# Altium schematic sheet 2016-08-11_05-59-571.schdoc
size 422 x 220 mm; SheetNumber: 1; SheetTotal: 1
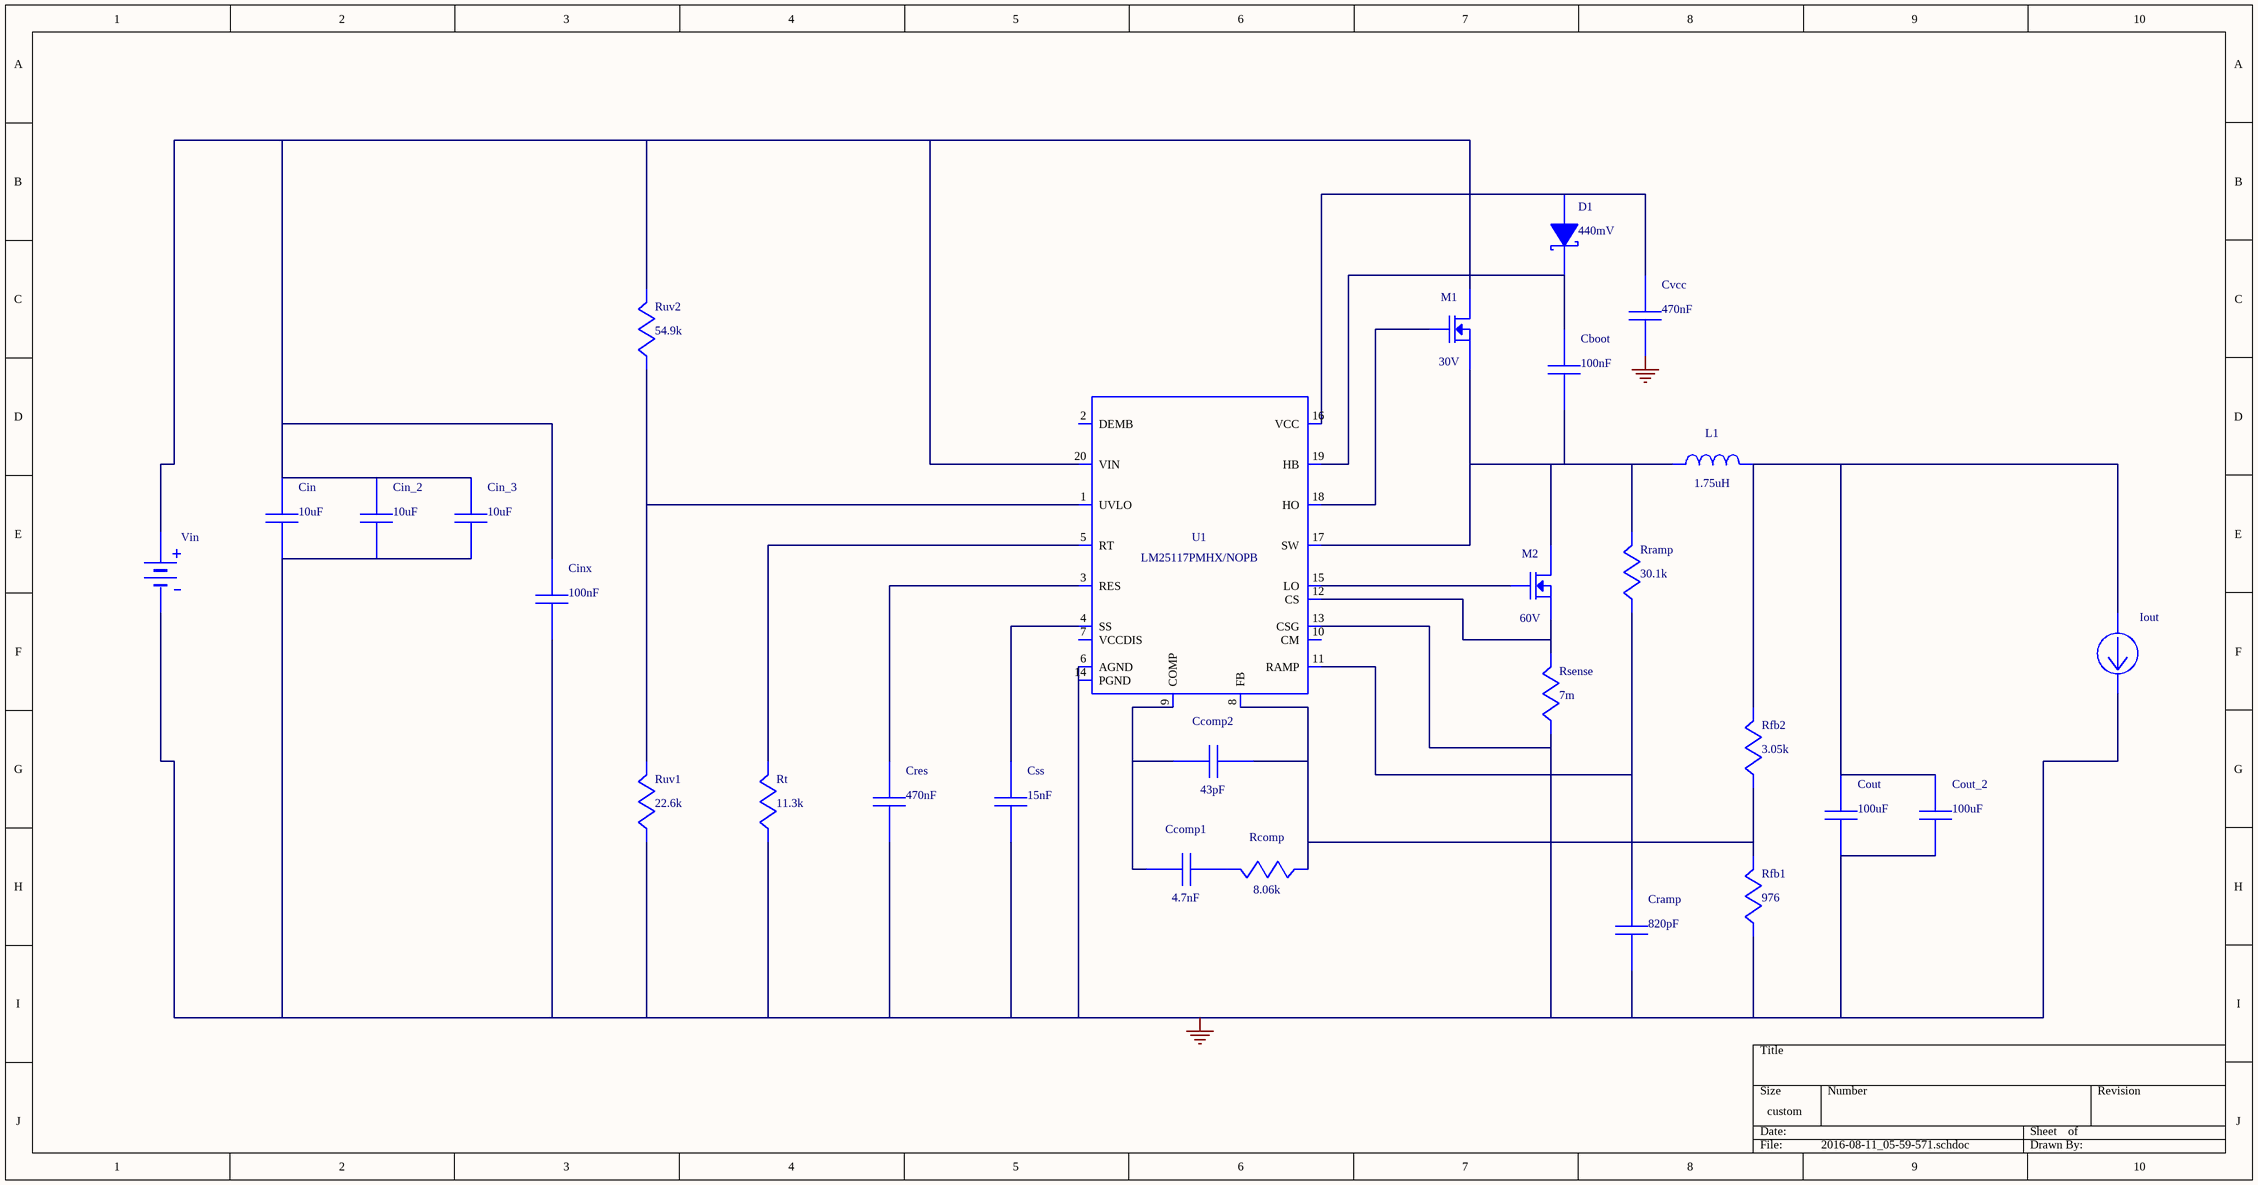
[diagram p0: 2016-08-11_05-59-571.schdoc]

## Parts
Cboot  value 100nF  (hidden comment: GRM155R61A104KA01D)
Ccomp1  value 4.7nF  (hidden comment: CC0805KRX7R9BB472)
Ccomp2  value 43pF  (hidden comment: CL21C430JBANNNC)
Cin  value 10uF  (hidden comment: GRM32ER7YA106KA12L)
Cin_2  value 10uF  (hidden comment: GRM32ER7YA106KA12L)
Cin_3  value 10uF  (hidden comment: GRM32ER7YA106KA12L)
Cinx  value 100nF  (hidden comment: C0805C104K5RACTU)
Cout  value 100uF  (hidden comment: GRM31CD80G107ME39L)
Cout_2  value 100uF  (hidden comment: GRM31CD80G107ME39L)
Cramp  value 820pF  (hidden comment: CC0805KRX7R9BB821)
Cres  value 470nF  (hidden comment: GRM155C80J474KE19D)
Css  value 15nF  (hidden comment: CC0805KRX7R9BB153)
Cvcc  value 470nF  (hidden comment: GRM155R61A474KE15D)
D1  value 440mV  (hidden comment: CD0603-B0130L)
Iout  WB_CURRENT_LOAD  (value not drawn)
L1  value 1.75uH  (hidden comment: MLC1260-172MLB)
M1  value 30V  (hidden comment: CSD17308Q3)
M2  value 60V  (hidden comment: CSD18531Q5A)
Rcomp  value 8.06k  (hidden comment: CRCW04028K06FKED)
Rfb1  value 976  (hidden comment: CRCW0402976RFKED)
Rfb2  value 3.05k  (hidden comment: RT0805BRD073K05L)
Rramp  value 30.1k  (hidden comment: CRCW040230K1FKED)
Rsense  value 7m  (hidden comment: PRL1632-R007-F-T1)
Rt  value 11.3k  (hidden comment: CRCW040211K3FKED)
Ruv1  value 22.6k  (hidden comment: CRCW040222K6FKED)
Ruv2  value 54.9k  (hidden comment: CRCW040254K9FKED)
U1  LM5117PMHX/NOPB  (value not drawn)
Vin  WB_BATTERY  (value not drawn)

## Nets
0: Cin.2 Cin_2.2 Cin_3.2 Cinx.2 Cout.2 Cout_2.2 Cramp.2 Cres.2 Css.2 Cvcc.2 Iout.2(-) Rfb1.2 Rsense.2 Rt.2 Ruv1.2 U1.6(AGND) U1.13(CSG) U1.14(PGND) U1.21(EP) Vin.2(-)
NetCboot_1: Cboot.1 D1.1(K) U1.19(HB)
NetCboot_2: Cboot.2 L1.1 M1.1(Source) M1.2(Source) M1.3(Source) M2.5(Drain) M2.6(Drain) M2.7(Drain) M2.8(Drain) M2.9(Drain) Rramp.1 U1.17(SW)
NetCcomp1_1: Ccomp1.1 Ccomp2.1 U1.9(COMP)
NetCcomp1_2: Ccomp1.2 Rcomp.1
NetCcomp2_2: Ccomp2.2 Rcomp.2 Rfb1.1 Rfb2.2 U1.8(FB)
NetCin_1: Cin.1 Cin_2.1 Cin_3.1 Cinx.1 M1.5(Drain) M1.6(Drain) M1.7(Drain) M1.8(Drain) M1.9(Drain) Ruv2.1 U1.20(VIN) Vin.1(+)
NetCout_1: Cout.1 Cout_2.1 Iout.1(+) L1.2 Rfb2.1
NetCramp_1: Cramp.1 Rramp.2 U1.11(RAMP)
NetCres_1: Cres.1 U1.3(RES)
NetCss_1: Css.1 U1.4(SS)
NetCvcc_1: Cvcc.1 D1.2(A) U1.16(VCC)
NetM1_4: M1.4(Gate) U1.18(HO)
NetM2_1: M2.1(Source) M2.2(Source) M2.3(Source) Rsense.1 U1.12(CS)
NetM2_4: M2.4(Gate) U1.15(LO)
NetRt_1: Rt.1 U1.5(RT)
NetRuv1_1: Ruv1.1 Ruv2.2 U1.1(UVLO)

Not connected (* = marked no-connect by the designer): U1 2(DEMB) 7(VCCDIS) 10(CM)

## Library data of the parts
Cboot = GRM155R61A104KA01D: GRM155R61A104KA0; Manufacturer Name: MuRata
Ccomp1 = CC0805KRX7R9BB472: CC0805KRX7R9BB47; Manufacturer Name: Yageo America
Ccomp2 = CL21C430JBANNNC: Manufacturer Name: Samsung Electro-Mechanics
Cin Cin_2 Cin_3 = GRM32ER7YA106KA12L: GRM32ER7YA106KA1; Manufacturer Name: MuRata
Cinx = C0805C104K5RACTU: Manufacturer Name: Kemet
Cout Cout_2 = GRM31CD80G107ME39L: GRM31CD80G107ME3; Manufacturer Name: MuRata
Cramp = CC0805KRX7R9BB821: CC0805KRX7R9BB82; Manufacturer Name: Yageo America
Cres = GRM155C80J474KE19D: GRM155C80J474KE1; Manufacturer Name: MuRata
Css = CC0805KRX7R9BB153: CC0805KRX7R9BB15; Manufacturer Name: Yageo America
Cvcc = GRM155R61A474KE15D: GRM155R61A474KE1; Manufacturer Name: MuRata
D1 = CD0603-B0130L: Manufacturer Name: Bourns
L1 = MLC1260-172MLB: Manufacturer Name: Coilcraft
M1 = CSD17308Q3: Manufacturer Name: Texas Instruments
M2 = CSD18531Q5A: Manufacturer Name: Texas Instruments
Rcomp = CRCW04028K06FKED: Manufacturer Name: Vishay-Dale
Rfb1 = CRCW0402976RFKED: Manufacturer Name: Vishay-Dale
Rfb2 = RT0805BRD073K05L: Manufacturer Name: Yageo America
Rramp = CRCW040230K1FKED: Manufacturer Name: Vishay-Dale
Rsense = PRL1632-R007-F-T1: PRL1632-R007-F-T; Manufacturer Name: Susumu Co Ltd
Rt = CRCW040211K3FKED: Manufacturer Name: Vishay-Dale
Ruv1 = CRCW040222K6FKED: Manufacturer Name: Vishay-Dale
Ruv2 = CRCW040254K9FKED: Manufacturer Name: Vishay-Dale
U1 = LM5117PMHX/NOPB: LM25117PMHX/NOPB; Manufacturer Name: Texas Instruments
